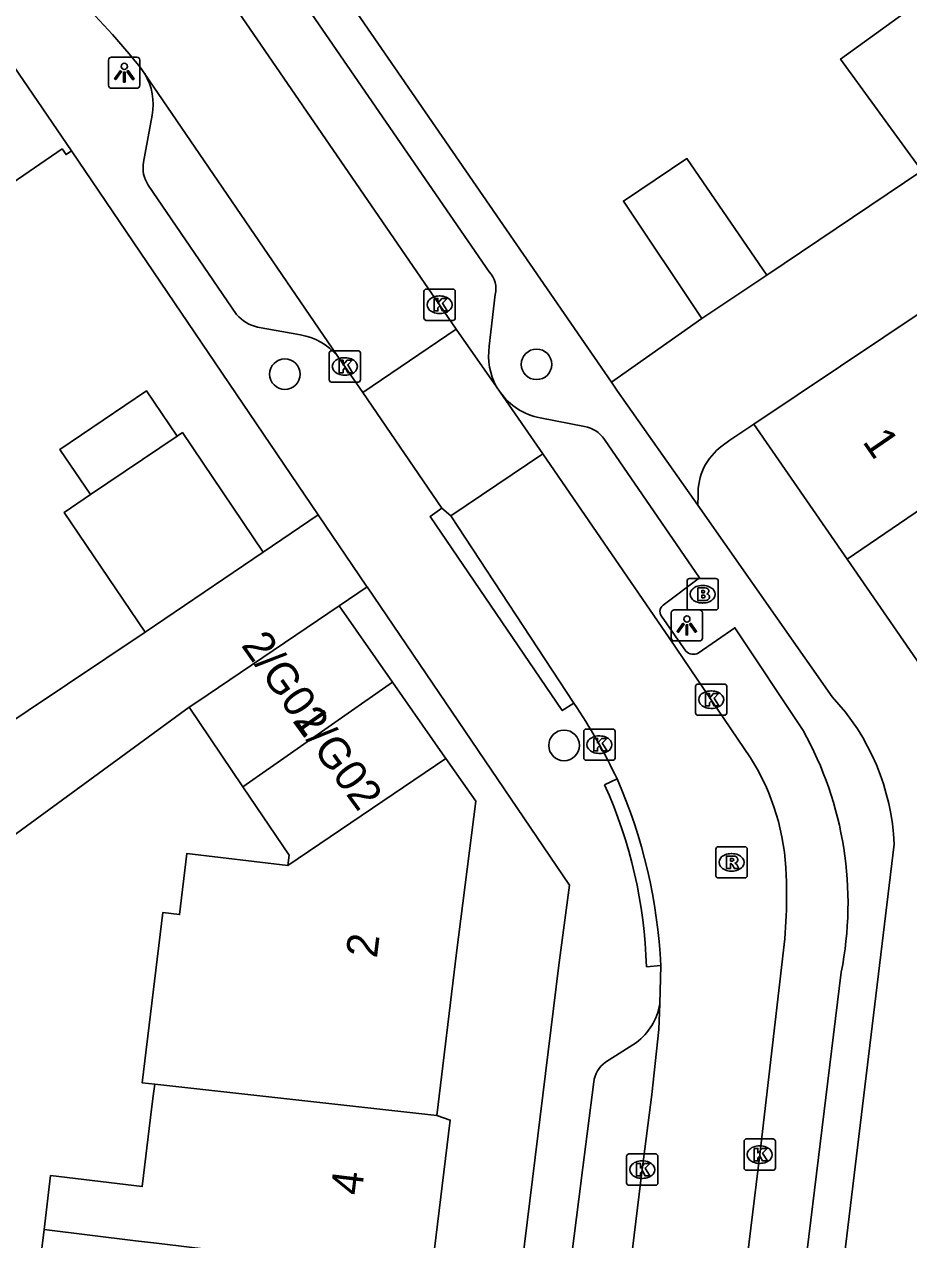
# Model space of a CAD drawing. Extents: x 158087 to 159494, y 382905 to 383981.
# Drawn here: x 158300.16 to 158328.44, y 383370.44 to 383409.32 of the extents above; entities that cross this region are included whole.
import ezdxf

# ---------------------------------------------------------------- set-up
doc = ezdxf.new("R2010")
doc.units = 0
for name, color, linetype in [('IMGEO_Boom', 7, 'Continuous'), ('IMGEO_Brandkraan', 7, 'Continuous'), ('IMGEO_Kolk', 7, 'Continuous'), ('IMGEO_Lichtpunt', 7, 'Continuous'), ('IMGEO_Pand', 7, 'Continuous'), ('IMGEO_Pand_nummerreeks', 7, 'Continuous'), ('IMGEO_Rijbaan_lokaal_open', 7, 'Continuous'), ('IMGEO_Rioolput', 7, 'Continuous'), ('IMGEO_Voetpad_open', 7, 'Continuous')]:
    doc.layers.add(name, color=color, linetype=linetype)

msp = doc.modelspace()

# ---------------------------------------------------------------- linework, layer by layer
at = {"layer": 'IMGEO_Boom'}
for centre in [(158308.493, 383398.125), (158316.54, 383398.439), (158317.419, 383386.252)]:
    msp.add_circle(centre, 0.489, dxfattribs=at)
at = {"layer": 'IMGEO_Brandkraan'}
for p, q in [((158321.35, 383390.66), (158321.35, 383391.512)), ((158321.425, 383391.586), (158322.277, 383391.586)), ((158321.838, 383391.366), (158321.863, 383391.366)), ((158322.351, 383391.512), (158322.351, 383390.66)), ((158322.277, 383390.586), (158321.425, 383390.586)), ((158321.861, 383390.806), (158321.836, 383390.806))]:
    msp.add_line(p, q, dxfattribs=at)
for points in [[(158321.35, 383390.66), (158321.35, 383391.512)], [(158321.425, 383391.586), (158322.277, 383391.586)], [(158321.698, 383391.286), (158321.698, 383390.886), (158321.911, 383390.886)], [(158321.929, 383391.286), (158321.698, 383391.286)], [(158321.877, 383391.205), (158321.823, 383391.205), (158321.823, 383391.129)], [(158322.351, 383391.512), (158322.351, 383390.66)], [(158321.823, 383391.129), (158321.876, 383391.129)], [(158321.885, 383391.053), (158321.823, 383391.053), (158321.823, 383390.972)], [(158321.823, 383390.972), (158321.885, 383390.972)], [(158322.277, 383390.586), (158321.425, 383390.586)]]:
    msp.add_lwpolyline(points, dxfattribs=at)
for centre, radius, start, end in [((158321.427, 383391.51), 0.0765, 91.552, 178.448), ((158321.427, 383391.51), 0.0765, 91.552, 178.448), ((158321.878, 383391.167), 0.0379, 267.8285, 90.9355), ((158321.933, 383391.141), 0.145, 59.4692, 91.5367), ((158321.958, 383391.188), 0.0922, 285.5137, 58.1501), ((158322.275, 383391.51), 0.0765, 1.552, 88.448), ((158322.275, 383391.51), 0.0765, 1.552, 88.448), ((158321.886, 383391.012), 0.0404, 269.8759, 90.5077), ((158321.917, 383391.137), 0.251, 268.6676, 293.5347), ((158321.963, 383390.996), 0.105, 301.3115, 78.989), ((158321.427, 383390.662), 0.0765, 181.552, 268.448), ((158321.427, 383390.662), 0.0765, 181.552, 268.448), ((158322.275, 383390.662), 0.0765, 271.552, 358.448), ((158322.275, 383390.662), 0.0765, 271.552, 358.448)]:
    msp.add_arc(centre, radius, start, end, dxfattribs=at)
for centre, major_axis, ratio, start_param, end_param in [((158321.837, 383391.086), (-0.387, 0.002), 0.722429, 4.712389, 7.853982), ((158321.862, 383391.086), (-0.39, 0.002), 0.717154, 1.570796, 4.712389)]:
    msp.add_ellipse(centre, major_axis=major_axis, ratio=ratio, start_param=start_param, end_param=end_param, dxfattribs=at)
at = {"layer": 'IMGEO_Kolk'}
for p, q in [((158312.94, 383399.92), (158312.94, 383400.772)), ((158313.015, 383400.846), (158313.867, 383400.846)), ((158313.428, 383400.626), (158313.453, 383400.626)), ((158313.941, 383400.772), (158313.941, 383399.92)), ((158313.867, 383399.846), (158313.015, 383399.846)), ((158313.451, 383400.066), (158313.426, 383400.066)), ((158309.909, 383397.946), (158309.909, 383398.798)), ((158309.984, 383398.872), (158310.836, 383398.872)), ((158310.397, 383398.652), (158310.422, 383398.652)), ((158310.91, 383398.798), (158310.91, 383397.946)), ((158310.836, 383397.872), (158309.984, 383397.872)), ((158310.42, 383398.092), (158310.395, 383398.092)), ((158321.623, 383387.288), (158321.623, 383388.14)), ((158321.698, 383388.214), (158322.55, 383388.214)), ((158322.624, 383388.14), (158322.624, 383387.288)), ((158322.111, 383387.994), (158322.136, 383387.994)), ((158322.134, 383387.434), (158322.109, 383387.434)), ((158322.55, 383387.214), (158321.698, 383387.214)), ((158318.049, 383385.849), (158318.049, 383386.701)), ((158318.124, 383386.775), (158318.976, 383386.775)), ((158318.537, 383386.555), (158318.562, 383386.555)), ((158319.05, 383386.701), (158319.05, 383385.849)), ((158318.976, 383385.775), (158318.124, 383385.775)), ((158318.56, 383385.995), (158318.535, 383385.995)), ((158323.174, 383372.737), (158323.174, 383373.589)), ((158323.249, 383373.663), (158324.101, 383373.663)), ((158323.662, 383373.443), (158323.687, 383373.443)), ((158324.175, 383373.589), (158324.175, 383372.737)), ((158319.419, 383372.257), (158319.419, 383373.109)), ((158319.494, 383373.183), (158320.346, 383373.183)), ((158319.907, 383372.963), (158319.932, 383372.963)), ((158320.42, 383373.109), (158320.42, 383372.257)), ((158324.101, 383372.663), (158323.249, 383372.663)), ((158323.685, 383372.883), (158323.66, 383372.883)), ((158320.346, 383372.183), (158319.494, 383372.183)), ((158319.93, 383372.403), (158319.905, 383372.403))]:
    msp.add_line(p, q, dxfattribs=at)
for points in [[(158312.94, 383399.92), (158312.94, 383400.772)], [(158313.015, 383400.846), (158313.867, 383400.846)], [(158313.261, 383400.546), (158313.384, 383400.546), (158313.384, 383400.395), (158313.514, 383400.546), (158313.678, 383400.546), (158313.532, 383400.395), (158313.685, 383400.146), (158313.533, 383400.146), (158313.448, 383400.31), (158313.384, 383400.243), (158313.384, 383400.146), (158313.261, 383400.146), (158313.261, 383400.546)], [(158313.941, 383400.772), (158313.941, 383399.92)], [(158313.867, 383399.846), (158313.015, 383399.846)], [(158309.909, 383397.946), (158309.909, 383398.798)], [(158309.984, 383398.872), (158310.836, 383398.872)], [(158310.91, 383398.798), (158310.91, 383397.946)], [(158310.23, 383398.572), (158310.353, 383398.572), (158310.353, 383398.421), (158310.483, 383398.572), (158310.647, 383398.572), (158310.501, 383398.421), (158310.654, 383398.172), (158310.502, 383398.172), (158310.417, 383398.336), (158310.353, 383398.269), (158310.353, 383398.172), (158310.23, 383398.172), (158310.23, 383398.572)], [(158310.836, 383397.872), (158309.984, 383397.872)], [(158321.623, 383387.288), (158321.623, 383388.14)], [(158321.698, 383388.214), (158322.55, 383388.214)], [(158322.624, 383388.14), (158322.624, 383387.288)], [(158321.944, 383387.914), (158322.067, 383387.914), (158322.067, 383387.763), (158322.197, 383387.914), (158322.361, 383387.914), (158322.215, 383387.763), (158322.368, 383387.514), (158322.216, 383387.514), (158322.131, 383387.678), (158322.067, 383387.611), (158322.067, 383387.514), (158321.944, 383387.514), (158321.944, 383387.914)], [(158322.55, 383387.214), (158321.698, 383387.214)], [(158318.049, 383385.849), (158318.049, 383386.701)], [(158318.124, 383386.775), (158318.976, 383386.775)], [(158319.05, 383386.701), (158319.05, 383385.849)], [(158318.37, 383386.475), (158318.493, 383386.475), (158318.493, 383386.324), (158318.623, 383386.475), (158318.787, 383386.475), (158318.641, 383386.324), (158318.794, 383386.075), (158318.642, 383386.075), (158318.557, 383386.239), (158318.493, 383386.172), (158318.493, 383386.075), (158318.37, 383386.075), (158318.37, 383386.475)], [(158318.976, 383385.775), (158318.124, 383385.775)], [(158323.174, 383372.737), (158323.174, 383373.589)], [(158323.249, 383373.663), (158324.101, 383373.663)], [(158323.495, 383373.363), (158323.618, 383373.363), (158323.618, 383373.212), (158323.748, 383373.363), (158323.912, 383373.363), (158323.766, 383373.212), (158323.919, 383372.963), (158323.767, 383372.963), (158323.682, 383373.127), (158323.618, 383373.06), (158323.618, 383372.963), (158323.495, 383372.963), (158323.495, 383373.363)], [(158324.175, 383373.589), (158324.175, 383372.737)], [(158319.419, 383372.257), (158319.419, 383373.109)], [(158319.494, 383373.183), (158320.346, 383373.183)], [(158320.42, 383373.109), (158320.42, 383372.257)], [(158319.74, 383372.883), (158319.863, 383372.883), (158319.863, 383372.732), (158319.993, 383372.883), (158320.157, 383372.883), (158320.011, 383372.732), (158320.164, 383372.483), (158320.012, 383372.483), (158319.927, 383372.647), (158319.863, 383372.58), (158319.863, 383372.483), (158319.74, 383372.483), (158319.74, 383372.883)], [(158324.101, 383372.663), (158323.249, 383372.663)], [(158320.346, 383372.183), (158319.494, 383372.183)]]:
    msp.add_lwpolyline(points, dxfattribs=at)
for centre, start, end in [((158313.017, 383400.77), 91.552, 178.448), ((158313.017, 383400.77), 91.552, 178.448), ((158313.865, 383400.77), 1.552, 88.448), ((158313.865, 383400.77), 1.552, 88.448), ((158313.017, 383399.922), 181.552, 268.448), ((158313.017, 383399.922), 181.552, 268.448), ((158313.865, 383399.922), 271.552, 358.448), ((158313.865, 383399.922), 271.552, 358.448), ((158309.986, 383398.796), 91.552, 178.448), ((158309.986, 383398.796), 91.552, 178.448), ((158310.834, 383398.796), 1.552, 88.448), ((158310.834, 383398.796), 1.552, 88.448), ((158309.986, 383397.948), 181.552, 268.448), ((158309.986, 383397.948), 181.552, 268.448), ((158310.834, 383397.948), 271.552, 358.448), ((158310.834, 383397.948), 271.552, 358.448), ((158321.7, 383388.138), 91.552, 178.448), ((158321.7, 383388.138), 91.552, 178.448), ((158322.548, 383388.138), 1.552, 88.448), ((158322.548, 383388.138), 1.552, 88.448), ((158321.7, 383387.29), 181.552, 268.448), ((158321.7, 383387.29), 181.552, 268.448), ((158322.548, 383387.29), 271.552, 358.448), ((158322.548, 383387.29), 271.552, 358.448), ((158318.126, 383386.699), 91.552, 178.448), ((158318.126, 383386.699), 91.552, 178.448), ((158318.974, 383386.699), 1.552, 88.448), ((158318.974, 383386.699), 1.552, 88.448), ((158318.126, 383385.851), 181.552, 268.448), ((158318.126, 383385.851), 181.552, 268.448), ((158318.974, 383385.851), 271.552, 358.448), ((158318.974, 383385.851), 271.552, 358.448), ((158323.251, 383373.587), 91.552, 178.448), ((158323.251, 383373.587), 91.552, 178.448), ((158324.099, 383373.587), 1.552, 88.448), ((158324.099, 383373.587), 1.552, 88.448), ((158319.496, 383373.107), 91.552, 178.448), ((158319.496, 383373.107), 91.552, 178.448), ((158320.344, 383373.107), 1.552, 88.448), ((158320.344, 383373.107), 1.552, 88.448), ((158323.251, 383372.739), 181.552, 268.448), ((158323.251, 383372.739), 181.552, 268.448), ((158324.099, 383372.739), 271.552, 358.448), ((158324.099, 383372.739), 271.552, 358.448), ((158319.496, 383372.259), 181.552, 268.448), ((158319.496, 383372.259), 181.552, 268.448), ((158320.344, 383372.259), 271.552, 358.448), ((158320.344, 383372.259), 271.552, 358.448)]:
    msp.add_arc(centre, 0.0765, start, end, dxfattribs=at)
for centre, major_axis, ratio, start_param, end_param in [((158313.427, 383400.346), (-0.387, 0.002), 0.722429, 4.712389, 7.853982), ((158313.452, 383400.346), (-0.39, 0.002), 0.717154, 1.570796, 4.712389), ((158310.396, 383398.372), (-0.387, 0.002), 0.722429, 4.712389, 7.853982), ((158310.421, 383398.372), (-0.39, 0.002), 0.717154, 1.570796, 4.712389), ((158322.11, 383387.714), (-0.387, 0.002), 0.722429, 4.712389, 7.853982), ((158322.135, 383387.714), (-0.39, 0.002), 0.717154, 1.570796, 4.712389), ((158318.536, 383386.275), (-0.387, 0.002), 0.722429, 4.712389, 7.853982), ((158318.561, 383386.275), (-0.39, 0.002), 0.717154, 1.570796, 4.712389), ((158323.661, 383373.163), (-0.387, 0.002), 0.722429, 4.712389, 7.853982), ((158323.686, 383373.163), (-0.39, 0.002), 0.717154, 1.570796, 4.712389), ((158319.906, 383372.683), (-0.387, 0.002), 0.722429, 4.712389, 7.853982), ((158319.931, 383372.683), (-0.39, 0.002), 0.717154, 1.570796, 4.712389)]:
    msp.add_ellipse(centre, major_axis=major_axis, ratio=ratio, start_param=start_param, end_param=end_param, dxfattribs=at)
at = {"layer": 'IMGEO_Lichtpunt'}
for p, q in [((158302.858, 383408.171), (158302.858, 383407.364)), ((158302.858, 383408.171), (158302.858, 383407.364)), ((158303.76, 383408.266), (158302.952, 383408.266)), ((158303.76, 383408.266), (158302.952, 383408.266)), ((158303.854, 383407.364), (158303.854, 383408.171)), ((158303.854, 383407.364), (158303.854, 383408.171)), ((158302.952, 383407.27), (158303.76, 383407.27)), ((158302.952, 383407.27), (158303.76, 383407.27)), ((158320.847, 383390.493), (158320.847, 383389.686)), ((158320.847, 383390.493), (158320.847, 383389.686)), ((158321.749, 383390.588), (158320.941, 383390.588)), ((158321.749, 383390.588), (158320.941, 383390.588)), ((158321.843, 383389.686), (158321.843, 383390.493)), ((158321.843, 383389.686), (158321.843, 383390.493)), ((158320.941, 383389.592), (158321.749, 383389.592)), ((158320.941, 383389.592), (158321.749, 383389.592))]:
    msp.add_line(p, q, dxfattribs=at)
for points in [[(158303.232, 383407.835), (158303.271, 383407.807), (158303.083, 383407.545), (158303.045, 383407.572), (158303.232, 383407.835)], [(158303.334, 383407.787), (158303.381, 383407.787), (158303.381, 383407.465), (158303.334, 383407.465), (158303.334, 383407.787)], [(158303.444, 383407.807), (158303.482, 383407.834), (158303.669, 383407.572), (158303.63, 383407.544), (158303.444, 383407.807)], [(158321.221, 383390.157), (158321.26, 383390.129), (158321.072, 383389.867), (158321.034, 383389.894), (158321.221, 383390.157)], [(158321.323, 383390.109), (158321.37, 383390.109), (158321.37, 383389.787), (158321.323, 383389.787), (158321.323, 383390.109)], [(158321.433, 383390.129), (158321.471, 383390.156), (158321.658, 383389.894), (158321.619, 383389.866), (158321.433, 383390.129)]]:
    msp.add_lwpolyline(points, dxfattribs=at)
for centre in [(158303.357, 383407.969), (158321.346, 383390.291)]:
    msp.add_circle(centre, 0.0994, dxfattribs=at)
for centre, start, end in [((158302.952, 383408.171), 90, 180), ((158302.952, 383408.171), 90, 180), ((158303.76, 383408.171), 0, 90), ((158303.76, 383408.171), 0, 90), ((158302.952, 383407.364), 180, 270), ((158302.952, 383407.364), 180, 270), ((158303.76, 383407.364), 270, 0), ((158303.76, 383407.364), 270, 360), ((158320.941, 383390.493), 90, 180), ((158320.941, 383390.493), 90, 180), ((158321.749, 383390.493), 0, 90), ((158321.749, 383390.493), 0, 90), ((158320.941, 383389.686), 180, 270), ((158320.941, 383389.686), 180, 270), ((158321.749, 383389.686), 270, 0), ((158321.749, 383389.686), 270, 360)]:
    msp.add_arc(centre, 0.0946, start, end, dxfattribs=at)
at = {"layer": 'IMGEO_Pand'}
for points in [[(158296.89, 383412.261), (158301.675, 383405.273)], [(158331.716, 383406.574), (158329.057, 383410.235), (158326.259, 383408.204), (158328.856, 383404.628)], [(158301.675, 383405.273), (158301.494, 383405.149), (158301.37, 383405.331), (158296.94, 383402.298)], [(158321.829, 383399.902), (158319.317, 383403.66), (158321.349, 383405.018), (158323.903, 383401.288)], [(158323.49, 383396.531), (158327.647, 383399.31), (158331.231, 383401.705)], [(158323.903, 383401.288), (158321.829, 383399.902)], [(158302.278, 383394.273), (158301.301, 383395.718), (158304.072, 383397.592), (158305.049, 383396.147)], [(158326.471, 383392.206), (158334.168, 383397.452)], [(158305.049, 383396.147), (158305.214, 383396.258), (158307.802, 383392.43)], [(158326.471, 383392.206), (158323.49, 383396.531)], [(158302.278, 383394.273), (158305.049, 383396.147)], [(158304.026, 383389.877), (158301.437, 383393.704), (158302.278, 383394.273)], [(158307.802, 383392.43), (158304.026, 383389.877)], [(158329.715, 383388.275), (158329.339, 383388.045), (158326.471, 383392.206)], [(158305.433, 383387.473), (158305.675, 383387.637), (158310.229, 383390.716)], [(158311.936, 383388.272), (158310.229, 383390.716)], [(158307.153, 383384.93), (158311.936, 383388.272)], [(158311.936, 383388.272), (158313.537, 383385.981), (158313.644, 383385.828)], [(158305.433, 383387.473), (158307.153, 383384.93)], [(158313.644, 383385.828), (158308.589, 383382.406)], [(158313.353, 383374.416), (158313.981, 383379.615), (158314.596, 383384.465), (158313.644, 383385.828)], [(158307.153, 383384.93), (158308.63, 383382.745), (158308.589, 383382.406)], [(158308.589, 383382.406), (158305.361, 383382.795), (158305.124, 383380.841), (158304.587, 383380.906), (158303.925, 383375.461), (158304.329, 383375.416)], [(158304.329, 383375.416), (158304.283, 383375.04), (158304.199, 383374.347), (158303.93, 383372.139), (158301.003, 383372.495), (158300.792, 383370.766)], [(158313.353, 383374.416), (158304.329, 383375.416)], [(158313.218, 383369.715), (158313.778, 383374.266), (158313.353, 383374.416)], [(158303.13, 383365.561), (158303.478, 383368.424), (158300.55, 383368.78), (158300.792, 383370.766)], [(158300.792, 383370.766), (158303.72, 383370.408), (158304.383, 383370.329), (158307.282, 383369.976), (158307.198, 383369.283), (158310.375, 383368.896), (158310.514, 383370.044), (158313.218, 383369.715)]]:
    msp.add_lwpolyline(points, dxfattribs=at)
at = {"layer": 'IMGEO_Rijbaan_lokaal_open'}
for points in [[(158313.971, 383399.562), (158313.439, 383400.345), (158305.308, 383412.194), (158302.976, 383415.583)], [(158304.009, 383407.737), (158303.897, 383407.901)], [(158304.009, 383407.737), (158310.169, 383398.717)], [(158310.982, 383397.538), (158313.971, 383399.562)], [(158313.971, 383399.562), (158315.258, 383397.722)], [(158310.982, 383397.538), (158310.411, 383398.372), (158310.169, 383398.717)], [(158313.515, 383393.84), (158310.982, 383397.538)], [(158315.258, 383397.722), (158315.376, 383397.552)], [(158315.376, 383397.552), (158316.738, 383395.573)], [(158316.738, 383395.573), (158313.796, 383393.595)], [(158323.38, 383385.854), (158322.124, 383387.713), (158320.779, 383389.691), (158316.738, 383395.573)], [(158313.515, 383393.84), (158313.796, 383393.595)], [(158313.796, 383393.595), (158317.732, 383387.605)], [(158320.476, 383377.982), (158320.511, 383379.214)], [(158322.25, 383361.466), (158323.674, 383373.162), (158324.368, 383379.15)], [(158320.476, 383377.982), (158320.452, 383377.164), (158320.227, 383375.082), (158319.921, 383372.682), (158317.996, 383356.929), (158315.726, 383338.441), (158315.42, 383336.079)]]:
    msp.add_lwpolyline(points, dxfattribs=at)
for centre, radius, start, end in [((158283.985, 383391.99), 25.488, 38.6275, 45.927), ((158303.077, 383377.663), 17.709, 25.113, 34.1527), ((158317.165, 383381.915), 7.358, 1.4032, 32.3669), ((158303.804, 383378.442), 16.725, 2.6451, 23.7534), ((158308.651, 383381.443), 15.883, 351.6993, 2.3527)]:
    msp.add_arc(centre, radius, start, end, dxfattribs=at)
at = {"layer": 'IMGEO_Rioolput'}
for p, q in [((158322.275, 383382.085), (158322.275, 383382.937)), ((158322.35, 383383.011), (158323.202, 383383.011)), ((158322.763, 383382.791), (158322.788, 383382.791)), ((158323.276, 383382.937), (158323.276, 383382.085)), ((158323.202, 383382.011), (158322.35, 383382.011)), ((158322.786, 383382.231), (158322.761, 383382.231))]:
    msp.add_line(p, q, dxfattribs=at)
for points in [[(158322.275, 383382.085), (158322.275, 383382.937)], [(158322.35, 383383.011), (158323.202, 383383.011)], [(158322.864, 383382.709), (158322.612, 383382.711), (158322.612, 383382.311)], [(158323.276, 383382.937), (158323.276, 383382.085)], [(158322.612, 383382.311), (158322.736, 383382.311), (158322.736, 383382.473), (158322.747, 383382.473)], [(158322.79, 383382.63), (158322.736, 383382.63), (158322.736, 383382.549)], [(158322.736, 383382.549), (158322.788, 383382.549)], [(158322.794, 383382.444), (158322.865, 383382.311), (158323.005, 383382.311), (158322.94, 383382.437)], [(158323.202, 383382.011), (158322.35, 383382.011)]]:
    msp.add_lwpolyline(points, dxfattribs=at)
for centre, radius, start, end in [((158322.352, 383382.935), 0.0765, 91.552, 178.448), ((158322.352, 383382.935), 0.0765, 91.552, 178.448), ((158322.863, 383382.599), 0.109, 350.3612, 89.416), ((158323.2, 383382.935), 0.0765, 1.552, 88.448), ((158323.2, 383382.935), 0.0765, 1.552, 88.448), ((158322.746, 383382.42), 0.0533, 26.0293, 88.6989), ((158322.772, 383382.738), 0.19, 274.7715, 282.9687), ((158322.796, 383382.534), 0.0964, 77.0061, 93.1865), ((158322.81, 383382.591), 0.0378, 276.6634, 79.6772), ((158322.861, 383382.599), 0.112, 277.5842, 350.9817), ((158322.845, 383382.384), 0.108, 29.5134, 73.7905), ((158322.352, 383382.087), 0.0765, 181.552, 268.448), ((158322.352, 383382.087), 0.0765, 181.552, 268.448), ((158323.2, 383382.087), 0.0765, 271.552, 358.448), ((158323.2, 383382.087), 0.0765, 271.552, 358.448)]:
    msp.add_arc(centre, radius, start, end, dxfattribs=at)
for centre, major_axis, ratio, start_param, end_param in [((158322.762, 383382.511), (-0.387, 0.002), 0.722429, 4.712389, 7.853982), ((158322.787, 383382.511), (-0.39, 0.002), 0.717154, 1.570796, 4.712389)]:
    msp.add_ellipse(centre, major_axis=major_axis, ratio=ratio, start_param=start_param, end_param=end_param, dxfattribs=at)
at = {"layer": 'IMGEO_Voetpad_open'}
for points in [[(158305.946, 383414.606), (158315.023, 383401.397)], [(158309.947, 383410.918), (158318.931, 383397.868)], [(158303.976, 383404.905), (158304.245, 383406.405)], [(158309.562, 383393.621), (158301.675, 383405.273)], [(158328.856, 383404.628), (158323.903, 383401.288)], [(158306.95, 383400.033), (158304.125, 383404.168)], [(158315.215, 383400.675), (158315.027, 383399.02)], [(158321.829, 383399.902), (158318.931, 383397.868)], [(158308.989, 383399.379), (158307.616, 383399.631)], [(158318.931, 383397.868), (158319.129, 383397.581), (158321.692, 383393.93)], [(158316.653, 383396.724), (158318.075, 383396.452)], [(158322.475, 383395.832), (158322.724, 383396.019), (158323.49, 383396.531)], [(158318.707, 383396.036), (158321.753, 383391.611), (158320.633, 383390.764)], [(158321.692, 383393.93), (158321.703, 383394.251)], [(158325.989, 383387.809), (158321.692, 383393.93)], [(158307.802, 383392.43), (158309.562, 383393.621)], [(158311.12, 383391.319), (158311.105, 383391.342), (158309.562, 383393.621)], [(158317.732, 383387.605), (158317.362, 383387.367), (158313.133, 383393.57), (158313.515, 383393.84)], [(158311.12, 383391.319), (158317.588, 383381.778), (158317.256, 383379.22), (158312.006, 383336.596), (158309.154, 383312.647), (158308.137, 383304.132)], [(158310.229, 383390.716), (158311.12, 383391.319)], [(158320.537, 383390.387), (158321.314, 383389.267)], [(158297.787, 383385.704), (158304.026, 383389.877)], [(158321.711, 383389.202), (158322.881, 383390.013), (158325.065, 383386.725)], [(158295.978, 383380.132), (158296.012, 383380.586), (158305.433, 383387.473)], [(158318.716, 383384.986), (158319.112, 383385.179)], [(158318.267, 383303.291), (158319.275, 383311.616), (158322.163, 383335.236), (158325.326, 383361.214), (158327.974, 383383.09)], [(158320.511, 383379.214), (158320.054, 383379.171)], [(158326.281, 383378.997), (158324.461, 383364.095)], [(158318.742, 383376.119), (158319.73, 383376.749)], [(158318.709, 383366.789), (158317.289, 383366.959), (158317.967, 383372.327), (158317.968, 383372.338), (158318.366, 383375.486)]]:
    msp.add_lwpolyline(points, dxfattribs=at)
for centre, radius, start, end in [((158302.415, 383406.768), 1.866, 348.7914, 31.3031), ((158304.9, 383404.708), 0.944, 167.9717, 214.8873), ((158314.48, 383400.866), 0.759, 345.4242, 44.3596), ((158307.863, 383400.792), 1.187, 219.7633, 258.006), ((158308.679, 383397.444), 1.96, 40.5172, 80.8964), ((158317.067, 383398.713), 2.062, 171.4515, 208.7306), ((158317.04, 383398.719), 2.032, 215.0524, 259.0293), ((158317.931, 383395.545), 0.918, 32.3191, 80.9728), ((158323.582, 383394.312), 1.88, 126.0808, 181.8668), ((158320.722, 383390.541), 0.24, 111.7294, 219.698), ((158321.557, 383389.508), 0.342, 224.7048, 296.6983), ((158320.622, 383382.775), 7.358, 2.4565, 43.1706), ((158315.166, 383381.208), 11.333, 348.7514, 29.1329), ((158304.904, 383378.747), 15.156, 1.605, 24.3108), ((158318.608, 383378.27), 1.89, 306.4105, 351.2393), ((158319.27, 383375.377), 0.91, 125.4301, 173.1495)]:
    msp.add_arc(centre, radius, start, end, dxfattribs=at)

# ---------------------------------------------------------------- texts
at = {"layer": 'IMGEO_Pand_nummerreeks'}
for s, rotation, p in [('1', 304.5776, (158326.939, 383395.967)), ('2/G01', 305.1455, (158307.074, 383389.452)), ('2/G02', 306.1354, (158308.714, 383387.039)), ('2', 82.9471, (158311.433, 383379.427)), ('4', 82.9872, (158310.941, 383371.838))]:
    msp.add_text(s, height=1, rotation=rotation, dxfattribs=at).set_placement(p)

doc.saveas('drawing.dxf')
